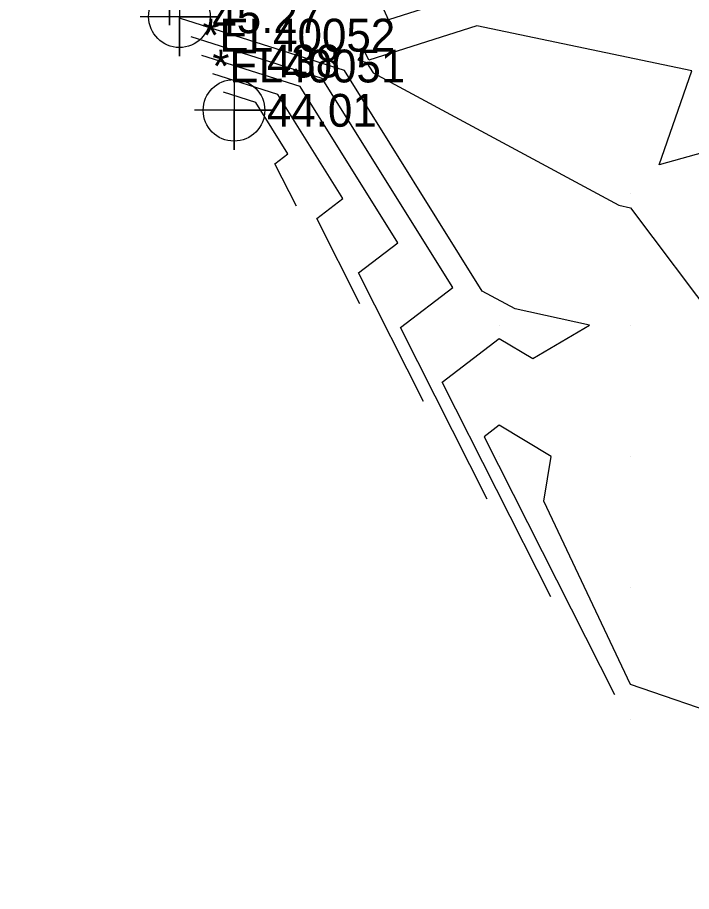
# Model space of a CAD drawing. Extents: x 2090860 to 2091277, y 159470 to 160080.
# Drawn here: x 2090993.3 to 2091044.6, y 159616.9 to 159683.4 of the extents above; entities that cross this region are included whole.
import ezdxf

# ---------------------------------------------------------------- set-up
doc = ezdxf.new("R2010")
doc.units = 0
for name, color, linetype in [('DTM Contours Major', 7, 'Continuous'), ('DTM Contours Minor', 7, 'Continuous'), ('Exist DTM Breakline Cogo Comment', 7, 'Continuous'), ('Exist DTM Breakline Cogo Elevation', 7, 'Continuous'), ('Exist DTM Breakline Cogo Point CELL', 7, 'Continuous'), ('Exist DTM QL2 LIDAR Elevation Point', 7, 'Continuous'), ('Exist DTM Regular Point Underwater CELL', 7, 'Continuous'), ('Exist DTM Regular Point Underwater Cogo Elevation', 7, 'Continuous'), ('Exist DTM Regular Point Underwater Cogo Number', 7, 'Continuous')]:
    doc.layers.add(name, color=color, linetype=linetype)

msp = doc.modelspace()

# ---------------------------------------------------------------- linework, layer by layer
at = {"layer": 'DTM Contours Major'}
msp.add_lwpolyline([(2091029.094, 159646.747), (2091022.487, 159659.808), (2091026.467, 159662.861), (2091016.541, 159678.756), (2091006.57, 159681.918)], dxfattribs=at)
at = {"layer": 'DTM Contours Minor'}
for points in [[(2091048.314, 159691.724), (2091021.574, 159683.222), (2091016.425, 159694.709), (2091022.839, 159712.491), (2091024.398, 159723.792), (2091024.683, 159724.953), (2091024.183, 159725.117), (2091023.648, 159724.57), (2091015.023, 159715.324), (2090993.617, 159699.85), (2090993.345, 159699.616)], [(2091033.936, 159639.312), (2091025.669, 159655.654), (2091030, 159658.977), (2091032.558, 159657.442), (2091036.867, 159660), (2091031.224, 159661.224), (2091028.711, 159662.577), (2091018.229, 159679.363), (2091005.753, 159683.32)], [(2091050, 159674.366), (2091042.178, 159672.178), (2091044.668, 159679.336), (2091028.311, 159682.77), (2091020.074, 159680.151), (2091019.761, 159680.848), (2091019.257, 159680.179), (2091019.917, 159679.97), (2091020.409, 159679.183), (2091039.113, 159669.113), (2091040, 159668.921), (2091046.718, 159660)], [(2091024.252, 159654.182), (2091019.305, 159663.961), (2091022.285, 159666.247), (2091014.853, 159678.148), (2091007.387, 159680.516)], [(2091019.41, 159661.617), (2091016.123, 159668.115), (2091018.103, 159669.634), (2091013.165, 159677.541), (2091008.205, 159679.115)], [(2091014.568, 159669.053), (2091012.941, 159672.268), (2091013.921, 159673.02), (2091011.477, 159676.934), (2091009.022, 159677.713)], [(2091046.552, 159616.895), (2091047.512, 159622.488), (2091047.686, 159630), (2091040, 159632.655), (2091033.409, 159646.591), (2091033.971, 159650), (2091030, 159652.382), (2091028.851, 159651.5), (2091038.778, 159631.877)]]:
    msp.add_lwpolyline(points, dxfattribs=at)
at = {"layer": 'Exist DTM Breakline Cogo Point CELL'}
for points in [[(2091004.908, 159688.809), (2091004.908, 159682.809), (2091004.908, 159685.809), (2091007.908, 159685.809), (2091001.908, 159685.809)], [(2091005.671, 159686.46), (2091005.671, 159680.46), (2091005.671, 159683.46), (2091008.671, 159683.46), (2091002.671, 159683.46)]]:
    msp.add_lwpolyline(points, dxfattribs=at)
msp.add_circle((2091005.671, 159683.46), 2.344, dxfattribs=at)
at = {"layer": 'Exist DTM QL2 LIDAR Elevation Point'}
for p, q in [((2091020, 159680), (2091020, 159680)), ((2091040, 159670), (2091040, 159670)), ((2091030, 159660), (2091030, 159660)), ((2091040, 159660), (2091040, 159660)), ((2091030, 159650), (2091030, 159650)), ((2091040, 159650), (2091040, 159650)), ((2091040, 159640), (2091040, 159640)), ((2091040, 159630), (2091040, 159630))]:
    msp.add_line(p, q, dxfattribs=at)
at = {"layer": 'Exist DTM Regular Point Underwater CELL'}
msp.add_lwpolyline([(2091009.823, 159679.339), (2091009.823, 159673.339), (2091009.823, 159676.339), (2091012.823, 159676.339), (2091006.823, 159676.339)], dxfattribs=at)
msp.add_circle((2091009.823, 159676.339), 2.344, dxfattribs=at)

# ---------------------------------------------------------------- texts
at = {"layer": 'Exist DTM Breakline Cogo Comment'}
for s, p in [('*EL40052', (2091007.408, 159680.809)), ('*EL40051', (2091008.171, 159678.46))]:
    msp.add_text(s, height=2.5, dxfattribs=at).set_placement(p)
at = {"layer": 'Exist DTM Breakline Cogo Elevation'}
msp.add_text('45.27', height=2.5, dxfattribs=at).set_placement((2091008.171, 159682.21))
at = {"layer": 'Exist DTM Regular Point Underwater Cogo Elevation'}
msp.add_text('44.01', height=2.5, dxfattribs=at).set_placement((2091012.323, 159675.089))
at = {"layer": 'Exist DTM Regular Point Underwater Cogo Number'}
msp.add_text('438', height=2.5, dxfattribs=at).set_placement((2091012.323, 159678.839))

doc.saveas('drawing.dxf')
